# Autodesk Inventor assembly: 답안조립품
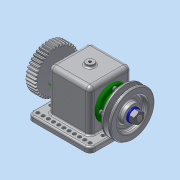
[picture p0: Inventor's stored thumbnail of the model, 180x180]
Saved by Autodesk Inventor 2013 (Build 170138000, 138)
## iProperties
Created: 2018-11
Part Number: 답안조립품
Document SubType Name: Assembly
Designer: dgall
Author: dgall
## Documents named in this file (13)
- C:\Users\dgall\Desktop\481107V1013\481107V1013\답안조립품.iam
- C:\Users\dgall\Desktop\481107V1013\481107V1013\본체.ipt
- C:\Users\dgall\Desktop\481107V1013\481107V1013\V벨트풀리.ipt
- C:\Users\dgall\Desktop\481107V1013\481107V1013\너트 M12x1.25.ipt
- C:\Users\dgall\Desktop\481107V1013\481107V1013\베어링 6203.ipt
- C:\Users\dgall\Desktop\481107V1013\481107V1013\볼트 M4.ipt
- C:\Users\dgall\Desktop\481107V1013\481107V1013\부시.ipt
- C:\Users\dgall\Desktop\481107V1013\481107V1013\스퍼기어.ipt
- C:\Users\dgall\Desktop\481107V1013\481107V1013\오일 실 26 38 8.ipt
- C:\Users\dgall\Desktop\481107V1013\481107V1013\와셔 12x24.ipt
- C:\Users\dgall\Desktop\481107V1013\481107V1013\축.ipt
- C:\Users\dgall\Desktop\481107V1013\481107V1013\커버.ipt
- C:\Users\dgall\Desktop\481107V1013\481107V1013\키 5x5x12.ipt
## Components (1 placed, 1 different names)
1. V벨트풀리:1
